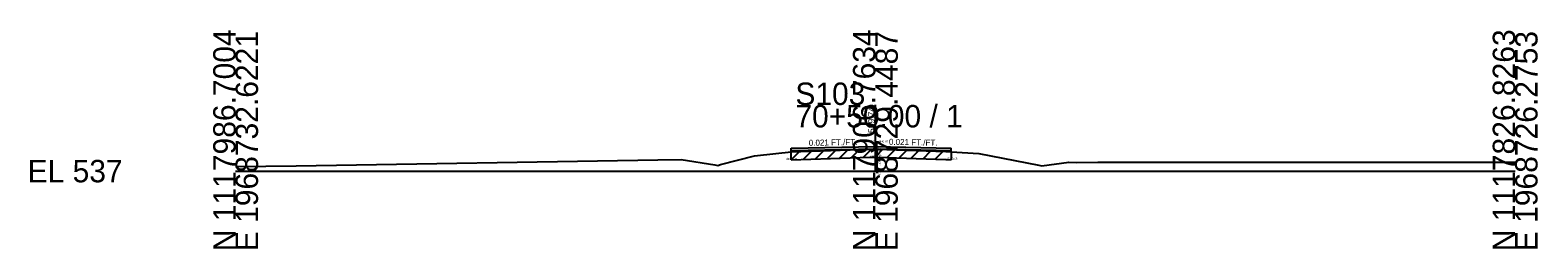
# Model space of a CAD drawing. Extents: x -26 to 163, y -10 to 24018.
# Drawn here: x -25.7 to 162.8, y 18490.3 to 18517.6 of the extents above; entities that cross this region are included whole.
import ezdxf

# ---------------------------------------------------------------- set-up
doc = ezdxf.new("R2010")
doc.units = 0
for name, color, linetype in [('RD_GPK_XS_Cell', 7, 'Continuous'), ('RD_XS_ExGround', 7, 'Continuous'), ('RD_XS_ExPaveRet', 7, 'Continuous'), ('RD_XS_Misc_Line', 7, 'Continuous'), ('RD_XS_PaveOvlay_CP', 7, 'Continuous'), ('RD_XS_TX_Elev_EX', 7, 'Continuous'), ('RD_XS_TX_ExEOP', 7, 'Continuous'), ('RD_XS_TX_Notes', 7, 'Continuous'), ('RD_XS_TX_Profile', 7, 'Continuous'), ('RD_XS_TX_Slope', 7, 'Continuous')]:
    doc.layers.add(name, color=color, linetype=linetype)

msp = doc.modelspace()

# ---------------------------------------------------------------- linework, layer by layer
at = {"layer": 'RD_GPK_XS_Cell'}
for p, q in [((80, 18500), (80, 18508.25)), ((0, 18500), (80, 18500)), ((80, 18500), (160, 18500))]:
    msp.add_line(p, q, dxfattribs=at)
at = {"layer": 'RD_XS_ExGround'}
msp.add_lwpolyline([(0, 18500.58), (7.58, 18500.65), (52.81, 18501.42), (55.72, 18501.46), (59.94, 18500.78), (60.31, 18500.72), (60.64, 18500.81), (64.88, 18501.9), (65.26, 18501.94), (69.47, 18502.4), (79.32, 18502.72), (80.17, 18502.75), (88.83, 18502.45), (89.47, 18502.42), (92.95, 18502.18), (100.46, 18500.73), (100.81, 18500.66), (104.19, 18501.13), (105.12, 18501.09), (107.83, 18501.12), (160, 18501.1)], dxfattribs=at)
at = {"layer": 'RD_XS_ExPaveRet'}
for p, q in [((75.47, 18501.59), (76.5, 18502.63)), ((76.97, 18501.64), (78, 18502.68)), ((78.47, 18501.69), (79.5, 18502.73)), ((79.97, 18501.74), (80.95, 18502.72)), ((81.47, 18501.7), (82.44, 18502.67)), ((82.97, 18501.65), (83.94, 18502.62)), ((69.47, 18501.4), (70.5, 18502.43)), ((69.47, 18501.4), (69.47, 18502.4)), ((69.47, 18501.4), (79.32, 18501.72)), ((70.97, 18501.45), (72, 18502.48)), ((72.47, 18501.5), (73.5, 18502.53)), ((73.97, 18501.54), (75, 18502.58)), ((79.32, 18501.72), (80.17, 18501.75)), ((80.17, 18501.75), (88.83, 18501.45)), ((84.47, 18501.6), (85.44, 18502.57)), ((85.97, 18501.55), (86.94, 18502.51)), ((87.47, 18501.49), (88.44, 18502.46)), ((88.83, 18501.45), (89.47, 18501.42)), ((89.47, 18502.42), (89.47, 18501.42))]:
    msp.add_line(p, q, dxfattribs=at)
at = {"layer": 'RD_XS_Misc_Line'}
msp.add_line((80.17, 18502.75), (80.17, 18499.75), dxfattribs=at)
at = {"layer": 'RD_XS_PaveOvlay_CP'}
for p, q in [((69.47, 18502.85), (80, 18503.07)), ((69.47, 18502.4), (69.47, 18502.85)), ((80, 18502.74), (69.47, 18502.53)), ((80, 18503.07), (89.47, 18502.88)), ((89.47, 18502.55), (80, 18502.74)), ((89.47, 18502.42), (89.47, 18502.88))]:
    msp.add_line(p, q, dxfattribs=at)

# ---------------------------------------------------------------- texts
at = {"layer": 'RD_GPK_XS_Cell'}
for s, p in [('N 1117986.7004', (0, 18490)), ('E 1968732.6221', (2.8, 18490)), ('N 1117906.7634', (80, 18490)), ('E 1968729.4487', (82.8, 18490)), ('N 1117826.8263', (160, 18490)), ('E 1968726.2753', (162.8, 18490))]:
    msp.add_text(s, height=2.8, rotation=90, dxfattribs=at).set_placement(p)
for s, p in [('S103', (70, 18508.25)), ('70+50.00 / 1', (70, 18505.45)), ('EL 537', (-26, 18498.6))]:
    msp.add_text(s, height=2.8, dxfattribs=at).set_placement(p)
at = {"layer": 'RD_XS_TX_Elev_EX'}
msp.add_text('539.74', height=0.8, rotation=90, dxfattribs=at).set_placement((79.9, 18504.74))
at = {"layer": 'RD_XS_TX_ExEOP'}
for s, p in [('EOP-L', (69.42, 18502.85)), ('EOP-R', (89.42, 18502.88))]:
    msp.add_text(s, height=0.1, rotation=270, dxfattribs=at).set_placement(p)
at = {"layer": 'RD_XS_TX_Notes'}
for s, p in [('Elev. @CL = 540.07', (78.48, 18503.57)), (' dE= 0.46', (68.76, 18501.4)), (' dE= 0.33', (79.29, 18501.74)), (' dE= 0.45', (88.76, 18501.42))]:
    msp.add_text(s, height=0.25, dxfattribs=at).set_placement(p)
msp.add_text(' Min. Distance @CP = -0.01', height=0.25, rotation=270, dxfattribs=at).set_placement((80.42, 18503.83))
at = {"layer": 'RD_XS_TX_Profile'}
msp.add_text('CL', height=0.25, dxfattribs=at).set_placement((79.77, 18503.07))
at = {"layer": 'RD_XS_TX_Slope'}
for rotation, p in [(1.1916, (71.68, 18503.15)), (358.8084, (81.69, 18503.29))]:
    msp.add_text('0.021 FT./FT.', height=0.75, rotation=rotation, dxfattribs=at).set_placement(p)

doc.saveas('drawing.dxf')
